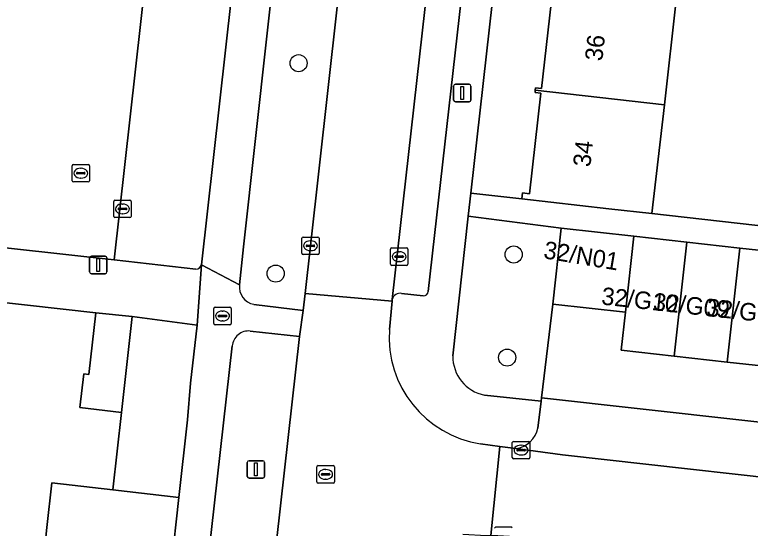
# Model space of a CAD drawing. Extents: x 161928 to 163071, y 386474 to 387428.
# Drawn here: x 162058.31 to 162100.36, y 386749.95 to 386779.32 of the extents above; entities that cross this region are included whole.
import ezdxf

# ---------------------------------------------------------------- set-up
doc = ezdxf.new("R2010")
doc.units = 0
for name, color, linetype in [('IMGEO_Boom', 7, 'Continuous'), ('IMGEO_Brandkraan', 7, 'Continuous'), ('IMGEO_Erf', 7, 'Continuous'), ('IMGEO_Groenvoorziening', 7, 'Continuous'), ('IMGEO_Haag', 7, 'Continuous'), ('IMGEO_Kolk', 7, 'Continuous'), ('IMGEO_Lichtmast', 7, 'Continuous'), ('IMGEO_Pand', 7, 'Continuous'), ('IMGEO_Pand_nummerreeks', 7, 'Continuous'), ('IMGEO_Parkeervlak_open', 7, 'Continuous'), ('IMGEO_Rijbaan_lokaal_open', 7, 'Continuous'), ('IMGEO_Rioolput', 7, 'Continuous'), ('IMGEO_Voetpad_open', 7, 'Continuous')]:
    doc.layers.add(name, color=color, linetype=linetype)

msp = doc.modelspace()

# ---------------------------------------------------------------- linework, layer by layer
at = {"layer": 'IMGEO_Boom'}
for centre in [(162074.54, 386776.543), (162086.835, 386765.606), (162073.23, 386764.516), (162086.465, 386759.713)]:
    msp.add_circle(centre, 0.489, dxfattribs=at)
at = {"layer": 'IMGEO_Brandkraan'}
for p, q in [((162069.765, 386762.59), (162070.617, 386762.59)), ((162069.69, 386761.664), (162069.69, 386762.516)), ((162070.178, 386762.37), (162070.203, 386762.37)), ((162070.691, 386762.516), (162070.691, 386761.664)), ((162069.949, 386762.084), (162069.949, 386762.096)), ((162070.387, 386762.047), (162069.989, 386762.047)), ((162069.992, 386762.133), (162070.39, 386762.133)), ((162070.201, 386761.81), (162070.176, 386761.81)), ((162070.433, 386762.096), (162070.433, 386762.084)), ((162070.617, 386761.59), (162069.765, 386761.59))]:
    msp.add_line(p, q, dxfattribs=at)
for points in [[(162069.765, 386762.59), (162070.617, 386762.59)], [(162069.69, 386761.664), (162069.69, 386762.516)], [(162070.691, 386762.516), (162070.691, 386761.664)], [(162070.617, 386761.59), (162069.765, 386761.59)]]:
    msp.add_lwpolyline(points, dxfattribs=at)
for centre, radius, start, end in [((162069.767, 386762.514), 0.0765, 91.552, 178.448), ((162069.767, 386762.514), 0.0765, 91.552, 178.448), ((162070.615, 386762.514), 0.0765, 1.552, 88.448), ((162070.615, 386762.514), 0.0765, 1.552, 88.448), ((162069.989, 386762.093), 0.0403, 85.8775, 175.7526), ((162069.986, 386762.083), 0.0366, 178.938, 274.7102), ((162070.39, 386762.09), 0.043, 264.8664, 352.4533), ((162070.394, 386762.095), 0.0386, 1.7309, 96.639), ((162069.767, 386761.666), 0.0765, 181.552, 268.448), ((162069.767, 386761.666), 0.0765, 181.552, 268.448), ((162070.615, 386761.666), 0.0765, 271.552, 358.448), ((162070.615, 386761.666), 0.0765, 271.552, 358.448)]:
    msp.add_arc(centre, radius, start, end, dxfattribs=at)
for centre, major_axis, ratio, start_param, end_param in [((162070.177, 386762.09), (-0.387, 0.002), 0.722429, 4.712389, 7.853982), ((162070.202, 386762.09), (-0.39, 0.002), 0.717154, 1.570796, 4.712389)]:
    msp.add_ellipse(centre, major_axis=major_axis, ratio=ratio, start_param=start_param, end_param=end_param, dxfattribs=at)
at = {"layer": 'IMGEO_Erf'}
for points in [[(162089.833, 386817.598), (162084.377, 386769.109), (162087.299, 386768.786), (162087.337, 386769.124), (162087.743, 386769.078), (162088.394, 386774.831), (162088.055, 386774.869), (162088.071, 386775.008), (162088.086, 386775.145), (162088.427, 386775.106), (162089.073, 386780.815)], [(162099.552, 386810.27), (162098.859, 386804.176), (162098.183, 386798.221), (162097.498, 386792.196), (162096.819, 386786.217), (162099.147, 386785.952), (162099.121, 386785.725), (162099.078, 386785.347), (162098.459, 386779.905), (162096.131, 386780.17), (162095.449, 386774.168), (162094.742, 386767.943), (162106.503, 386766.612)]]:
    msp.add_lwpolyline(points, dxfattribs=at)
at = {"layer": 'IMGEO_Groenvoorziening'}
for points in [[(162071.975, 386762.758), (162074.794, 386762.398), (162074.911, 386763.372), (162075.219, 386766.106), (162077.228, 386784.056), (162078.898, 386798.979)], [(162074.985, 386798.474), (162073.414, 386784.31), (162071.382, 386766.053), (162071.156, 386763.875)], [(162089.069, 386762.773), (162089.553, 386767.113), (162084.229, 386767.795), (162083.355, 386759.809)], [(162085.17, 386757.568), (162088.403, 386757.23), (162088.426, 386757.42), (162089.069, 386762.773)], [(162070.094, 386745.771), (162072.858, 386745.455), (162074.588, 386760.913)], [(162074.588, 386760.913), (162071.777, 386761.229)], [(162070.748, 386760.377), (162069.217, 386746.832)]]:
    msp.add_lwpolyline(points, dxfattribs=at)
msp.add_lwpolyline([(162068.367, 386758.248), (162068.744, 386761.57), (162065.031, 386762.071), (162064.418, 386756.573), (162063.926, 386752.159), (162067.69, 386751.715), (162068.197, 386756.147)], close=True, dxfattribs=at)
for centre, radius, start, end in [((162072.157, 386763.75), 1.008, 172.8691, 259.6297), ((162071.67, 386760.311), 0.924, 83.3516, 175.8971), ((162085.601, 386759.773), 2.246, 179.0738, 258.9347)]:
    msp.add_arc(centre, radius, start, end, dxfattribs=at)
at = {"layer": 'IMGEO_Haag'}
msp.add_lwpolyline([(162068.367, 386758.248), (162068.744, 386761.57), (162065.031, 386762.071), (162064.418, 386756.573), (162063.926, 386752.159), (162067.69, 386751.715), (162068.197, 386756.147)], close=True, dxfattribs=at)
at = {"layer": 'IMGEO_Kolk'}
for p, q in [((162063.968, 386767.788), (162063.968, 386768.64)), ((162064.043, 386768.714), (162064.895, 386768.714)), ((162064.456, 386768.494), (162064.481, 386768.494)), ((162064.969, 386768.64), (162064.969, 386767.788)), ((162064.227, 386768.208), (162064.227, 386768.22)), ((162064.665, 386768.171), (162064.267, 386768.171)), ((162064.27, 386768.257), (162064.668, 386768.257)), ((162064.711, 386768.22), (162064.711, 386768.208)), ((162064.895, 386767.714), (162064.043, 386767.714)), ((162064.479, 386767.934), (162064.454, 386767.934)), ((162074.718, 386765.68), (162074.718, 386766.532)), ((162074.793, 386766.606), (162075.645, 386766.606)), ((162075.206, 386766.386), (162075.231, 386766.386)), ((162075.719, 386766.532), (162075.719, 386765.68)), ((162074.977, 386766.1), (162074.977, 386766.112)), ((162075.415, 386766.063), (162075.017, 386766.063)), ((162075.02, 386766.149), (162075.418, 386766.149)), ((162075.461, 386766.112), (162075.461, 386766.1)), ((162079.862, 386765.985), (162080.714, 386765.985)), ((162075.645, 386765.606), (162074.793, 386765.606)), ((162075.229, 386765.826), (162075.204, 386765.826)), ((162079.787, 386765.059), (162079.787, 386765.911)), ((162080.089, 386765.528), (162080.487, 386765.528)), ((162080.275, 386765.765), (162080.3, 386765.765)), ((162080.788, 386765.911), (162080.788, 386765.059)), ((162080.046, 386765.479), (162080.046, 386765.491)), ((162080.484, 386765.442), (162080.086, 386765.442)), ((162080.298, 386765.205), (162080.273, 386765.205)), ((162080.53, 386765.491), (162080.53, 386765.479)), ((162080.714, 386764.985), (162079.862, 386764.985)), ((162086.756, 386753.998), (162086.756, 386754.85)), ((162086.831, 386754.924), (162087.683, 386754.924)), ((162087.244, 386754.704), (162087.269, 386754.704)), ((162087.757, 386754.85), (162087.757, 386753.998)), ((162087.015, 386754.418), (162087.015, 386754.43)), ((162087.453, 386754.381), (162087.055, 386754.381)), ((162087.058, 386754.467), (162087.456, 386754.467)), ((162087.499, 386754.43), (162087.499, 386754.418)), ((162087.683, 386753.924), (162086.831, 386753.924)), ((162087.267, 386754.144), (162087.242, 386754.144)), ((162085.82, 386750.028), (162086.672, 386750.028))]:
    msp.add_line(p, q, dxfattribs=at)
for points in [[(162063.968, 386767.788), (162063.968, 386768.64)], [(162064.043, 386768.714), (162064.895, 386768.714)], [(162064.969, 386768.64), (162064.969, 386767.788)], [(162064.895, 386767.714), (162064.043, 386767.714)], [(162074.718, 386765.68), (162074.718, 386766.532)], [(162074.793, 386766.606), (162075.645, 386766.606)], [(162075.719, 386766.532), (162075.719, 386765.68)], [(162079.862, 386765.985), (162080.714, 386765.985)], [(162075.645, 386765.606), (162074.793, 386765.606)], [(162079.787, 386765.059), (162079.787, 386765.911)], [(162080.788, 386765.911), (162080.788, 386765.059)], [(162080.714, 386764.985), (162079.862, 386764.985)], [(162086.756, 386753.998), (162086.756, 386754.85)], [(162086.831, 386754.924), (162087.683, 386754.924)], [(162087.757, 386754.85), (162087.757, 386753.998)], [(162087.683, 386753.924), (162086.831, 386753.924)], [(162085.82, 386750.028), (162086.672, 386750.028)]]:
    msp.add_lwpolyline(points, dxfattribs=at)
for centre, radius, start, end in [((162064.045, 386768.638), 0.0765, 91.552, 178.448), ((162064.045, 386768.638), 0.0765, 91.552, 178.448), ((162064.893, 386768.638), 0.0765, 1.552, 88.448), ((162064.893, 386768.638), 0.0765, 1.552, 88.448), ((162064.267, 386768.217), 0.0403, 85.8775, 175.7526), ((162064.264, 386768.207), 0.0366, 178.938, 274.7102), ((162064.668, 386768.214), 0.043, 264.8664, 352.4533), ((162064.672, 386768.219), 0.0386, 1.7309, 96.639), ((162064.045, 386767.79), 0.0765, 181.552, 268.448), ((162064.045, 386767.79), 0.0765, 181.552, 268.448), ((162064.893, 386767.79), 0.0765, 271.552, 358.448), ((162064.893, 386767.79), 0.0765, 271.552, 358.448), ((162074.795, 386766.53), 0.0765, 91.552, 178.448), ((162074.795, 386766.53), 0.0765, 91.552, 178.448), ((162075.643, 386766.53), 0.0765, 1.552, 88.448), ((162075.643, 386766.53), 0.0765, 1.552, 88.448), ((162075.017, 386766.109), 0.0403, 85.8775, 175.7526), ((162075.014, 386766.099), 0.0366, 178.938, 274.7102), ((162075.418, 386766.106), 0.043, 264.8664, 352.4533), ((162075.422, 386766.111), 0.0386, 1.7309, 96.639), ((162079.864, 386765.909), 0.0765, 91.552, 178.448), ((162079.864, 386765.909), 0.0765, 91.552, 178.448), ((162080.712, 386765.909), 0.0765, 1.552, 88.448), ((162080.712, 386765.909), 0.0765, 1.552, 88.448), ((162074.795, 386765.682), 0.0765, 181.552, 268.448), ((162074.795, 386765.682), 0.0765, 181.552, 268.448), ((162075.643, 386765.682), 0.0765, 271.552, 358.448), ((162075.643, 386765.682), 0.0765, 271.552, 358.448), ((162080.086, 386765.488), 0.0403, 85.8775, 175.7526), ((162080.491, 386765.49), 0.0386, 1.7309, 96.639), ((162080.083, 386765.478), 0.0366, 178.938, 274.7102), ((162080.487, 386765.485), 0.043, 264.8664, 352.4533), ((162079.864, 386765.061), 0.0765, 181.552, 268.448), ((162079.864, 386765.061), 0.0765, 181.552, 268.448), ((162080.712, 386765.061), 0.0765, 271.552, 358.448), ((162080.712, 386765.061), 0.0765, 271.552, 358.448), ((162086.833, 386754.848), 0.0765, 91.552, 178.448), ((162086.833, 386754.848), 0.0765, 91.552, 178.448), ((162087.681, 386754.848), 0.0765, 1.552, 88.448), ((162087.681, 386754.848), 0.0765, 1.552, 88.448), ((162087.055, 386754.427), 0.0403, 85.8775, 175.7526), ((162087.052, 386754.417), 0.0366, 178.938, 274.7102), ((162087.456, 386754.424), 0.043, 264.8664, 352.4533), ((162087.46, 386754.429), 0.0386, 1.7309, 96.639), ((162086.833, 386754), 0.0765, 181.552, 268.448), ((162086.833, 386754), 0.0765, 181.552, 268.448), ((162087.681, 386754), 0.0765, 271.552, 358.448), ((162087.681, 386754), 0.0765, 271.552, 358.448), ((162085.822, 386749.952), 0.0765, 91.552, 178.448), ((162085.822, 386749.952), 0.0765, 91.552, 178.448), ((162086.67, 386749.952), 0.0765, 1.552, 88.448), ((162086.67, 386749.952), 0.0765, 1.552, 88.448)]:
    msp.add_arc(centre, radius, start, end, dxfattribs=at)
for centre, major_axis, ratio, start_param, end_param in [((162064.455, 386768.214), (-0.387, 0.002), 0.722429, 4.712389, 7.853982), ((162064.48, 386768.214), (-0.39, 0.002), 0.717154, 1.570796, 4.712389), ((162075.205, 386766.106), (-0.387, 0.002), 0.722429, 4.712389, 7.853982), ((162075.23, 386766.106), (-0.39, 0.002), 0.717154, 1.570796, 4.712389), ((162080.274, 386765.485), (-0.387, 0.002), 0.722429, 4.712389, 7.853982), ((162080.299, 386765.485), (-0.39, 0.002), 0.717154, 1.570796, 4.712389), ((162087.243, 386754.424), (-0.387, 0.002), 0.722429, 4.712389, 7.853982), ((162087.268, 386754.424), (-0.39, 0.002), 0.717154, 1.570796, 4.712389)]:
    msp.add_ellipse(centre, major_axis=major_axis, ratio=ratio, start_param=start_param, end_param=end_param, dxfattribs=at)
at = {"layer": 'IMGEO_Lichtmast'}
for p, q in [((162083.403, 386774.438), (162083.403, 386775.238)), ((162083.403, 386775.238), (162083.403, 386774.438)), ((162083.503, 386775.338), (162084.293, 386775.338)), ((162084.293, 386775.338), (162083.503, 386775.338)), ((162084.393, 386775.238), (162084.393, 386774.438)), ((162084.393, 386774.438), (162084.393, 386775.238)), ((162084.293, 386774.338), (162083.503, 386774.338)), ((162083.503, 386774.338), (162084.293, 386774.338)), ((162062.591, 386764.611), (162062.591, 386765.411)), ((162062.591, 386765.411), (162062.591, 386764.611)), ((162062.691, 386765.511), (162063.481, 386765.511)), ((162063.481, 386765.511), (162062.691, 386765.511)), ((162063.581, 386765.411), (162063.581, 386764.611)), ((162063.581, 386764.611), (162063.581, 386765.411)), ((162063.481, 386764.511), (162062.691, 386764.511)), ((162062.691, 386764.511), (162063.481, 386764.511)), ((162071.706, 386753.819), (162072.496, 386753.819)), ((162072.496, 386753.819), (162071.706, 386753.819)), ((162071.606, 386752.919), (162071.606, 386753.719)), ((162071.606, 386753.719), (162071.606, 386752.919)), ((162072.596, 386753.719), (162072.596, 386752.919)), ((162072.596, 386752.919), (162072.596, 386753.719)), ((162072.496, 386752.819), (162071.706, 386752.819)), ((162071.706, 386752.819), (162072.496, 386752.819))]:
    msp.add_line(p, q, dxfattribs=at)
for points in [[(162083.823, 386775.213), (162083.973, 386775.213), (162083.973, 386774.463), (162083.823, 386774.463), (162083.823, 386775.213)], [(162063.011, 386765.386), (162063.161, 386765.386), (162063.161, 386764.636), (162063.011, 386764.636), (162063.011, 386765.386)], [(162072.026, 386753.694), (162072.176, 386753.694), (162072.176, 386752.944), (162072.026, 386752.944), (162072.026, 386753.694)]]:
    msp.add_lwpolyline(points, dxfattribs=at)
for centre, start, end in [((162083.503, 386775.238), 90, 180), ((162083.503, 386775.238), 90, 180), ((162084.293, 386775.238), 0, 90), ((162084.293, 386775.238), 360, 90), ((162083.503, 386774.438), 180, 270), ((162083.503, 386774.438), 180, 270), ((162084.293, 386774.438), 270, 0), ((162084.293, 386774.438), 270, 0), ((162062.691, 386765.411), 90, 180), ((162062.691, 386765.411), 90, 180), ((162063.481, 386765.411), 0, 90), ((162063.481, 386765.411), 360, 90), ((162062.691, 386764.611), 180, 270), ((162062.691, 386764.611), 180, 270), ((162063.481, 386764.611), 270, 0), ((162063.481, 386764.611), 270, 0), ((162071.706, 386753.719), 90, 180), ((162071.706, 386753.719), 90, 180), ((162072.496, 386753.719), 0, 90), ((162072.496, 386753.719), 360, 90), ((162071.706, 386752.919), 180, 270), ((162071.706, 386752.919), 180, 270), ((162072.496, 386752.919), 270, 0), ((162072.496, 386752.919), 270, 0)]:
    msp.add_arc(centre, 0.1, start, end, dxfattribs=at)
at = {"layer": 'IMGEO_Pand'}
for points in [[(162088.695, 386781.015), (162088.678, 386780.86), (162089.073, 386780.815), (162088.427, 386775.106), (162088.086, 386775.145), (162088.071, 386775.008), (162095.449, 386774.168), (162096.131, 386780.17)], [(162088.071, 386775.008), (162088.055, 386774.869), (162088.394, 386774.831), (162087.743, 386769.078), (162087.337, 386769.124), (162087.299, 386768.786), (162092.268, 386768.223), (162094.742, 386767.943), (162095.449, 386774.168)], [(162093.707, 386766.65), (162089.553, 386767.113), (162089.069, 386762.773), (162093.222, 386762.31)], [(162093.222, 386762.31), (162092.979, 386760.136), (162096.011, 386759.798), (162096.737, 386766.312), (162093.707, 386766.65)], [(162096.011, 386759.798), (162099.041, 386759.46), (162099.767, 386765.974), (162096.737, 386766.312)], [(162102.071, 386759.122), (162102.798, 386765.637), (162099.767, 386765.974), (162099.041, 386759.46)]]:
    msp.add_lwpolyline(points, close=True, dxfattribs=at)
msp.add_lwpolyline([(162044.512, 386725.13), (162058.594, 386723.562), (162058.991, 386727.12), (162058.664, 386727.157), (162058.874, 386729.041), (162061.439, 386728.755), (162061.947, 386733.315), (162058.415, 386733.71), (162058.842, 386737.538), (162063.946, 386736.971), (162065.168, 386747.944), (162059.991, 386748.52), (162060.155, 386750), (162060.438, 386752.547), (162063.926, 386752.159), (162064.418, 386756.573), (162062.04, 386756.866), (162062.254, 386758.784), (162062.552, 386758.75), (162062.945, 386762.278), (162048.824, 386763.85)], dxfattribs=at)
at = {"layer": 'IMGEO_Parkeervlak_open'}
for points in [[(162085.895, 386816.661), (162083.956, 386799.092), (162079.897, 386763.041)], [(162068.285, 386803.638), (162064.004, 386765.296), (162068.664, 386764.776)], [(162068.982, 386765.015), (162073.103, 386801.861)], [(162081.953, 386763.485), (162085.969, 386799.06)], [(162080.426, 386763.383), (162081.667, 386763.237)]]:
    msp.add_lwpolyline(points, dxfattribs=at)
for centre, radius, start, end in [((162068.673, 386765.096), 0.32, 268.4548, 345.4002), ((162081.661, 386763.533), 0.296, 271.2265, 350.6328), ((162080.336, 386762.941), 0.451, 78.5272, 167.2383)]:
    msp.add_arc(centre, radius, start, end, dxfattribs=at)
at = {"layer": 'IMGEO_Rijbaan_lokaal_open'}
for points in [[(162083.956, 386799.092), (162085.895, 386816.661), (162085.914, 386817.194), (162080.655, 386817.752), (162080.704, 386816.794), (162080.675, 386815.201), (162080.514, 386813.23), (162079.408, 386803.249), (162078.898, 386798.979), (162077.228, 386784.056), (162075.219, 386766.106), (162074.911, 386763.372), (162079.886, 386762.942), (162079.897, 386763.041)], [(162129.491, 386749.686), (162126.661, 386750), (162123.662, 386750.337), (162089.619, 386754.158), (162086.964, 386754.512), (162086.042, 386754.635), (162085.527, 386749.539), (162085.935, 386749.548), (162086.594, 386749.505), (162086.873, 386749.474), (162135.328, 386744.09), (162135.874, 386748.978), (162134.473, 386749.133)]]:
    msp.add_lwpolyline(points, close=True, dxfattribs=at)
for points in [[(162060.619, 386793.088), (162058.268, 386793.375), (162057.884, 386790.024), (162057.495, 386786.618), (162057.105, 386783.212), (162056.716, 386779.806), (162056.326, 386776.401), (162055.936, 386772.995), (162055.547, 386769.589), (162055.168, 386766.28), (162064.004, 386765.296), (162068.285, 386803.638), (162068.4, 386804.529)], [(162079.886, 386762.942), (162074.911, 386763.372), (162074.794, 386762.398), (162074.588, 386760.913), (162072.858, 386745.455), (162072.667, 386743.884), (162077.675, 386743.338), (162077.779, 386744.364)], [(162079.73, 386761.315), (162079.886, 386762.942)], [(162083.937, 386749.62), (162085.274, 386749.533), (162085.527, 386749.539), (162086.042, 386754.635), (162084.947, 386754.776)]]:
    msp.add_lwpolyline(points, dxfattribs=at)
msp.add_arc((162085.897, 386760.885), 6.182, 176.0082, 261.1595, dxfattribs=at)
at = {"layer": 'IMGEO_Rioolput'}
for p, q in [((162061.588, 386769.828), (162061.588, 386770.68)), ((162061.663, 386770.754), (162062.515, 386770.754)), ((162062.589, 386770.68), (162062.589, 386769.828)), ((162061.847, 386770.248), (162061.847, 386770.26)), ((162062.285, 386770.211), (162061.887, 386770.211)), ((162061.89, 386770.297), (162062.288, 386770.297)), ((162062.076, 386770.534), (162062.101, 386770.534)), ((162062.331, 386770.26), (162062.331, 386770.248)), ((162062.515, 386769.754), (162061.663, 386769.754)), ((162062.099, 386769.974), (162062.074, 386769.974)), ((162075.584, 386752.61), (162075.584, 386753.462)), ((162075.659, 386753.536), (162076.511, 386753.536)), ((162076.585, 386753.462), (162076.585, 386752.61)), ((162075.843, 386753.03), (162075.843, 386753.042)), ((162076.281, 386752.993), (162075.883, 386752.993)), ((162075.886, 386753.079), (162076.284, 386753.079)), ((162076.072, 386753.316), (162076.097, 386753.316)), ((162076.327, 386753.042), (162076.327, 386753.03)), ((162076.511, 386752.536), (162075.659, 386752.536)), ((162076.095, 386752.756), (162076.07, 386752.756))]:
    msp.add_line(p, q, dxfattribs=at)
for points in [[(162061.588, 386769.828), (162061.588, 386770.68)], [(162061.663, 386770.754), (162062.515, 386770.754)], [(162062.589, 386770.68), (162062.589, 386769.828)], [(162062.515, 386769.754), (162061.663, 386769.754)], [(162075.584, 386752.61), (162075.584, 386753.462)], [(162075.659, 386753.536), (162076.511, 386753.536)], [(162076.585, 386753.462), (162076.585, 386752.61)], [(162076.511, 386752.536), (162075.659, 386752.536)]]:
    msp.add_lwpolyline(points, dxfattribs=at)
for centre, radius, start, end in [((162061.665, 386770.678), 0.0765, 91.552, 178.448), ((162061.665, 386770.678), 0.0765, 91.552, 178.448), ((162062.513, 386770.678), 0.0765, 1.552, 88.448), ((162062.513, 386770.678), 0.0765, 1.552, 88.448), ((162061.887, 386770.257), 0.0403, 85.8775, 175.7526), ((162061.884, 386770.247), 0.0366, 178.938, 274.7102), ((162062.288, 386770.254), 0.043, 264.8664, 352.4533), ((162062.292, 386770.259), 0.0386, 1.7309, 96.639), ((162061.665, 386769.83), 0.0765, 181.552, 268.448), ((162061.665, 386769.83), 0.0765, 181.552, 268.448), ((162062.513, 386769.83), 0.0765, 271.552, 358.448), ((162062.513, 386769.83), 0.0765, 271.552, 358.448), ((162075.661, 386753.46), 0.0765, 91.552, 178.448), ((162075.661, 386753.46), 0.0765, 91.552, 178.448), ((162076.509, 386753.46), 0.0765, 1.552, 88.448), ((162076.509, 386753.46), 0.0765, 1.552, 88.448), ((162075.883, 386753.039), 0.0403, 85.8775, 175.7526), ((162075.88, 386753.029), 0.0366, 178.938, 274.7102), ((162076.284, 386753.036), 0.043, 264.8664, 352.4533), ((162076.288, 386753.041), 0.0386, 1.7309, 96.639), ((162075.661, 386752.612), 0.0765, 181.552, 268.448), ((162075.661, 386752.612), 0.0765, 181.552, 268.448), ((162076.509, 386752.612), 0.0765, 271.552, 358.448), ((162076.509, 386752.612), 0.0765, 271.552, 358.448)]:
    msp.add_arc(centre, radius, start, end, dxfattribs=at)
for centre, major_axis, ratio, start_param, end_param in [((162062.075, 386770.254), (-0.387, 0.002), 0.722429, 4.712389, 7.853982), ((162062.1, 386770.254), (-0.39, 0.002), 0.717154, 1.570796, 4.712389), ((162076.071, 386753.036), (-0.387, 0.002), 0.722429, 4.712389, 7.853982), ((162076.096, 386753.036), (-0.39, 0.002), 0.717154, 1.570796, 4.712389)]:
    msp.add_ellipse(centre, major_axis=major_axis, ratio=ratio, start_param=start_param, end_param=end_param, dxfattribs=at)
at = {"layer": 'IMGEO_Voetpad_open'}
for points in [[(162083.355, 386759.809), (162084.229, 386767.795), (162084.377, 386769.109), (162089.833, 386817.598), (162090.441, 386822.62), (162090.455, 386822.824), (162092.006, 386836.491), (162093.369, 386848.507), (162093.586, 386850.424), (162095.89, 386870.733)], [(162087.861, 386815.698), (162085.969, 386799.06), (162081.953, 386763.485)], [(162073.103, 386801.861), (162068.982, 386765.015), (162071.156, 386763.875), (162071.382, 386766.053), (162073.414, 386784.31), (162074.985, 386798.474)], [(162064.004, 386765.296), (162055.168, 386766.28), (162055.157, 386766.183), (162048.503, 386766.944), (162007.061, 386771.581), (162006.777, 386769.017), (162033.803, 386765.933), (162033.754, 386765.523), (162036.361, 386765.29), (162047.299, 386764.081), (162048.824, 386763.85), (162062.945, 386762.278), (162065.031, 386762.071), (162068.744, 386761.57), (162068.982, 386765.015)], [(162106.503, 386766.612), (162094.742, 386767.943), (162092.268, 386768.223), (162087.299, 386768.786), (162084.377, 386769.109), (162084.229, 386767.795), (162089.553, 386767.113), (162093.707, 386766.65), (162096.737, 386766.312), (162099.767, 386765.974), (162102.798, 386765.637)], [(162068.664, 386764.776), (162064.004, 386765.296)], [(162071.156, 386763.875), (162068.982, 386765.015), (162068.744, 386761.57), (162068.367, 386758.248), (162068.197, 386756.147), (162067.69, 386751.715), (162067.259, 386747.713), (162066.058, 386736.723), (162065.644, 386732.924), (162064.603, 386722.927), (162063.546, 386718.588)], [(162079.897, 386763.041), (162079.886, 386762.942), (162079.73, 386761.315)], [(162081.667, 386763.237), (162080.426, 386763.383)], [(162071.777, 386761.229), (162074.588, 386760.913), (162074.794, 386762.398), (162071.975, 386762.758)], [(162069.217, 386746.832), (162070.748, 386760.377)], [(162088.215, 386755.687), (162088.403, 386757.23), (162085.17, 386757.568)], [(162088.426, 386757.42), (162088.403, 386757.23), (162088.215, 386755.687)], [(162122.596, 386751.923), (162122.784, 386753.584), (162088.426, 386757.42)], [(162084.947, 386754.776), (162086.042, 386754.635), (162086.964, 386754.512)], [(162086.964, 386754.512), (162089.619, 386754.158), (162123.662, 386750.337)]]:
    msp.add_lwpolyline(points, dxfattribs=at)
for points in [[(162093.222, 386762.31), (162089.069, 386762.773), (162088.426, 386757.42), (162122.784, 386753.584), (162123.283, 386756.757), (162120.253, 386757.095), (162117.222, 386757.433), (162114.192, 386757.771), (162111.162, 386758.109), (162108.132, 386758.446), (162105.102, 386758.784), (162102.071, 386759.122), (162099.041, 386759.46), (162096.011, 386759.798), (162092.979, 386760.136)], [(162062.945, 386762.278), (162062.552, 386758.75), (162062.254, 386758.784), (162062.04, 386756.866), (162064.418, 386756.573), (162065.031, 386762.071)], [(162067.69, 386751.715), (162063.926, 386752.159), (162060.438, 386752.547), (162060.155, 386750), (162059.991, 386748.52), (162065.168, 386747.944), (162067.259, 386747.713)]]:
    msp.add_lwpolyline(points, close=True, dxfattribs=at)
for centre, radius, start, end in [((162068.673, 386765.096), 0.32, 268.4548, 345.4002), ((162072.157, 386763.75), 1.008, 172.8691, 259.6297), ((162081.661, 386763.533), 0.296, 271.2265, 350.6328), ((162080.336, 386762.941), 0.451, 78.5272, 167.2383), ((162085.897, 386760.885), 6.182, 176.0082, 261.1595), ((162071.67, 386760.311), 0.924, 83.3516, 175.8971), ((162085.601, 386759.773), 2.246, 179.0738, 258.9347), ((162086.778, 386755.964), 1.464, 277.3141, 349.0972), ((162086.778, 386755.964), 1.464, 277.3141, 349.0972)]:
    msp.add_arc(centre, radius, start, end, dxfattribs=at)

# ---------------------------------------------------------------- texts
at = {"layer": 'IMGEO_Pand_nummerreeks'}
for s, rotation, p in [('36', 83.5743, (162091.895, 386776.634)), ('34', 83.5743, (162091.213, 386770.579)), ('32/N01', 350.5377, (162088.497, 386765.4)), ('32/G10', 353.7671, (162091.815, 386762.753)), ('32/G09', 353.7671, (162094.77, 386762.43)), ('32/G08', 353.7671, (162097.828, 386762.096))]:
    msp.add_text(s, height=1, rotation=rotation, dxfattribs=at).set_placement(p)

doc.saveas('drawing.dxf')
